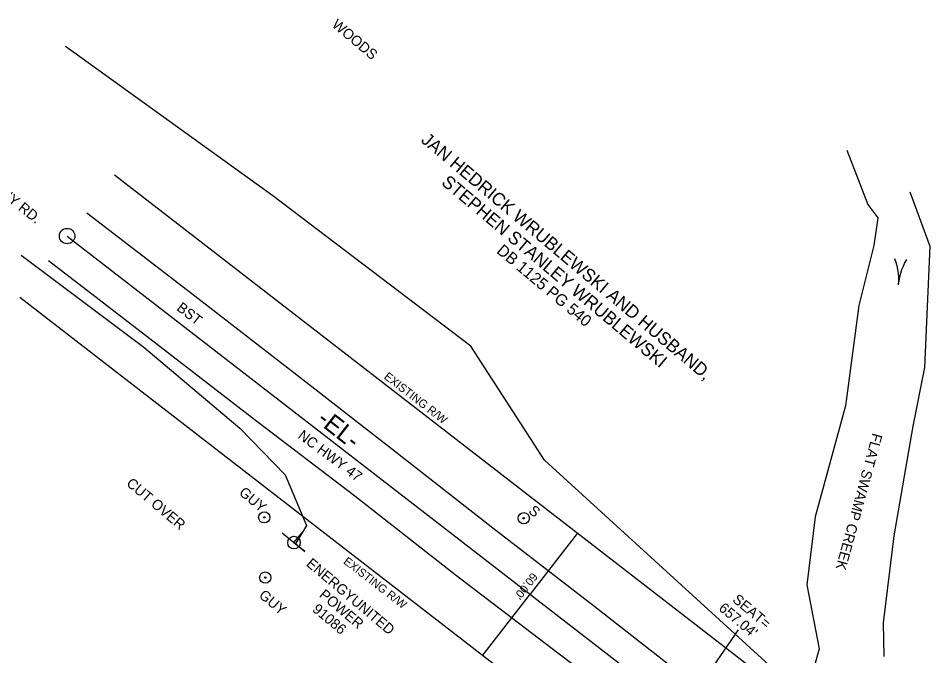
# Model space of a CAD drawing. Extents: x 1657485 to 1658542, y 706191 to 707067.
# Drawn here: x 1657802.6 to 1658156.4, y 706776.1 to 707023.7 of the extents above; entities that cross this region are included whole.
import ezdxf

# ---------------------------------------------------------------- set-up
doc = ezdxf.new("R2010")
doc.units = 0
for name, color, linetype in [('Exist Horizontal Alignment', 7, 'Continuous'), ('Exist Horizontal Alignment Direction Label', 7, 'Continuous'), ('Exist Horizontal Alignment Point', 7, 'Continuous'), ('Exist Hydro Stream Flow Arrow CELL', 7, 'Continuous'), ('Exist Hydro Stream or Body of Water', 7, 'Continuous'), ('Exist Hydro Stream or Body of Water Text', 7, 'Continuous'), ('Exist Other Culture Anchor (Guy Wire) CELL', 7, 'Continuous'), ('Exist Other Culture Anchor (Guy Wire) Text', 7, 'Continuous'), ('Exist Other Culture Located Object Leader', 7, 'Continuous'), ('Exist Other Culture Sign CELL', 7, 'Continuous'), ('Exist Other Culture Sign Text', 7, 'Continuous'), ('Exist Property Deed Book Text', 7, 'Continuous'), ('Exist Property Owner Text', 7, 'Continuous'), ('Exist Right of Way Line', 7, 'Continuous'), ('Exist Right of Way Line Text', 7, 'Continuous'), ('Exist Right of Way Width CELL', 7, 'Continuous'), ('Exist Roads EOP', 7, 'Continuous'), ('Exist Roads EOP Text', 7, 'Continuous'), ('Exist Structure Major Bridge Seat Top Elevation', 7, 'Continuous'), ('Exist Utilities Power Joint Use Telephone CELL', 7, 'Continuous'), ('Exist Utilities Power Joint Use Telephone Text', 7, 'Continuous'), ('Exist Utilities Telephone UG FO SUE LOS C', 7, 'Continuous'), ('Exist Vegetation Woods Line', 7, 'Continuous'), ('Old_Level_1', 7, 'Continuous')]:
    doc.layers.add(name, color=color, linetype=linetype)

msp = doc.modelspace()

# ---------------------------------------------------------------- linework, layer by layer
at = {"layer": 'Exist Horizontal Alignment'}
msp.add_line((1657821.54, 706939.11), (1658069.08, 706747.49), dxfattribs=at)
at = {"layer": 'Exist Horizontal Alignment Point'}
msp.add_circle((1657821.54, 706939.11), 3, dxfattribs=at)
at = {"layer": 'Exist Hydro Stream Flow Arrow CELL'}
msp.add_line((1658144.58, 706925.19), (1658144.58, 706925.19), dxfattribs=at)
for points in [[(1658142.74, 706930.38), (1658143.22, 706928.99), (1658143.56, 706927.53), (1658143.87, 706926.08), (1658144.06, 706924.65), (1658144.17, 706923.17), (1658144.2, 706921.68), (1658144.14, 706920.21)], [(1658147.3, 706929.97), (1658146.59, 706928.69), (1658146, 706927.31), (1658145.44, 706925.95), (1658145, 706924.57), (1658144.64, 706923.13), (1658144.35, 706921.66), (1658144.14, 706920.21)]]:
    msp.add_lwpolyline(points, dxfattribs=at)
at = {"layer": 'Exist Hydro Stream or Body of Water'}
for points in [[(1658124.22, 706972.45), (1658132.27, 706951.37), (1658136.16, 706946.2), (1658134.7, 706935.44), (1658128.81, 706912.12), (1658123.71, 706873.2), (1658111.95, 706830.1), (1658108.7, 706803.68), (1658113.38, 706778.75), (1658109.58, 706764.8), (1658099.83, 706752.59), (1658091.25, 706743.28), (1658080.45, 706734.89), (1658069.68, 706723.38), (1658063.35, 706716.36), (1658042.47, 706705.75), (1658012.94, 706689.18), (1657981.36, 706680.35), (1657950.92, 706664.28), (1657936.29, 706648.78), (1657910.94, 706618)], [(1658148.59, 706956.25), (1658156.37, 706935.24), (1658154.31, 706888.11), (1658149.78, 706865.29), (1658142.43, 706822.61), (1658138.27, 706788.84), (1658138.48, 706775.79)]]:
    msp.add_lwpolyline(points, dxfattribs=at)
at = {"layer": 'Exist Other Culture Anchor (Guy Wire) CELL'}
for centre, radius in [((1657898.06, 706829.83), 2.18), ((1657898.06, 706829.83), 0.24), ((1657898.45, 706806.44), 2.18), ((1657898.45, 706806.44), 0.24)]:
    msp.add_circle(centre, radius, dxfattribs=at)
at = {"layer": 'Exist Other Culture Located Object Leader'}
msp.add_line((1658068.41, 706766.22), (1658082.16, 706786.08), dxfattribs=at)
at = {"layer": 'Exist Other Culture Sign CELL'}
for radius in [2.18, 0.24]:
    msp.add_circle((1657998.77, 706829.49), radius, dxfattribs=at)
at = {"layer": 'Exist Right of Way Line'}
for p, q in [((1657839.91, 706962.84), (1658087.45, 706771.22)), ((1657803.18, 706915.39), (1658050.72, 706723.77))]:
    msp.add_line(p, q, dxfattribs=at)
at = {"layer": 'Exist Right of Way Width CELL'}
for p, q in [((1658019.55, 706823.61), (1658001.27, 706800.02)), ((1657982.92, 706776.32), (1658001.38, 706800.15))]:
    msp.add_line(p, q, dxfattribs=at)
at = {"layer": 'Exist Roads EOP'}
for points in [[(1657829.19, 706948.18), (1657868.22, 706918.15), (1657908.36, 706887.05), (1657947.4, 706856.64), (1657986.78, 706825.79), (1658025.82, 706795.57), (1658063.85, 706765.84), (1658066.09, 706765.17)], [(1657814.35, 706929.59), (1657853.7, 706899.35), (1657893.53, 706868.5), (1657933.27, 706838.23), (1657972.18, 706807.62), (1658012.04, 706777.15), (1658049.42, 706748.92), (1658050.79, 706746.94)]]:
    msp.add_lwpolyline(points, dxfattribs=at)
at = {"layer": 'Exist Utilities Power Joint Use Telephone CELL'}
msp.add_line((1657909.59, 706820.03), (1657909.59, 706820.03), dxfattribs=at)
msp.add_lwpolyline([(1657905, 706823.79), (1657913.75, 706816.58), (1657909.58, 706820.01), (1657913.16, 706824.38)], dxfattribs=at)
msp.add_circle((1657909.6, 706820.03), 2.45, dxfattribs=at)
at = {"layer": 'Exist Utilities Telephone UG FO SUE LOS C'}
msp.add_lwpolyline([(1657803.74, 706931.75), (1657851.28, 706895.97), (1657888.59, 706864.47), (1657906.17, 706846.3), (1657914.52, 706826.68), (1657910.3, 706819.84)], dxfattribs=at)
at = {"layer": 'Exist Vegetation Woods Line'}
msp.add_lwpolyline([(1658135.28, 706734.78), (1658006.85, 706852.11), (1657978.27, 706896.38), (1657901.37, 706954.71), (1657820.9, 707012.72)], dxfattribs=at)

# ---------------------------------------------------------------- texts
at = {"layer": 'Exist Horizontal Alignment Direction Label'}
msp.add_text('-EL-', height=7, rotation=321.8499, dxfattribs=at).set_placement((1657918.09, 706866.97))
at = {"layer": 'Exist Hydro Stream or Body of Water Text'}
msp.add_text('FLAT SWAMP CREEK', height=4, rotation=254.7315, dxfattribs=at).set_placement((1658134.21, 706862.78))
at = {"layer": 'Exist Other Culture Anchor (Guy Wire) Text'}
for p in [(1657887.95, 706838.96), (1657895.67, 706799.05)]:
    msp.add_text('GUY', height=4, rotation=319.9162, dxfattribs=at).set_placement(p)
at = {"layer": 'Exist Other Culture Sign Text'}
msp.add_text('S', height=4, rotation=319.9162, dxfattribs=at).set_placement((1658000.32, 706831.86))
at = {"layer": 'Exist Property Deed Book Text'}
msp.add_text('DB 1125 PG 540', height=4.5, rotation=319.9162, dxfattribs=at).set_placement((1657987.91, 706932.85))
at = {"layer": 'Exist Property Owner Text'}
for s, p in [('JAN HEDRICK WRUBLEWSKI AND HUSBAND,', (1657958.56, 706975.87)), ('STEPHEN STANLEY WRUBLEWSKI', (1657966.5, 706959.38))]:
    msp.add_text(s, height=5, rotation=319.9162, dxfattribs=at).set_placement(p)
at = {"layer": 'Exist Right of Way Line Text'}
for p in [(1657944.25, 706883.97), (1657928.51, 706812.18)]:
    msp.add_text('EXISTING R/W', height=3.2, rotation=322.2336, dxfattribs=at).set_placement(p)
at = {"layer": 'Exist Right of Way Width CELL'}
msp.add_text("60.00'", height=3.2, rotation=232.2336, dxfattribs=at).set_placement((1658001.96, 706808.63))
at = {"layer": 'Exist Roads EOP Text'}
for s, rotation, p in [('TO BETHANY RD.', 321.5478, (1657774.33, 706971.62)), ('BST', 322.186, (1657863.75, 706910.58)), ('NC HWY 47', 323.3192, (1657910.81, 706860.87))]:
    msp.add_text(s, height=4, rotation=rotation, dxfattribs=at).set_placement(p)
at = {"layer": 'Exist Structure Major Bridge Seat Top Elevation'}
for s, p in [('SEAT=', (1658079.5, 706797.35)), ("657.04'", (1658074.14, 706794.02))]:
    msp.add_text(s, height=4, rotation=319.9162, dxfattribs=at).set_placement(p)
at = {"layer": 'Exist Utilities Power Joint Use Telephone Text'}
for s, p in [('ENERGYUNITED', (1657914.05, 706811.29)), ('POWER', (1657919.08, 706799.21)), ('91086', (1657916.42, 706793.61))]:
    msp.add_text(s, height=4, rotation=319.9162, dxfattribs=at).set_placement(p)
at = {"layer": 'Old_Level_1'}
for s, p in [('WOODS', (1657923.99, 707020.69)), ('CUT OVER', (1657844.22, 706842.49))]:
    msp.add_text(s, height=4, rotation=319.9162, dxfattribs=at).set_placement(p)

doc.saveas('drawing.dxf')
